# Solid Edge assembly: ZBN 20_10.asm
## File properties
Title: Zylinder
Author: bmolnar
Template: iso metric assembly.asm
Last saved by: bmolnar
Revision: 9
Application: Solid Edge
Username: bmolnar
Dokumentum tartalom típus: 1
Document Number: ZBN 20/10
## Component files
Kit_1.par
Kit_2.par
Profilrohr.par
Kolbenstange.par
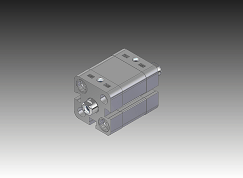
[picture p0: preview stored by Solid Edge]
